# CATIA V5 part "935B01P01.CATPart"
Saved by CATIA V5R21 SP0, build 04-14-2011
Part number: 935B01P01
Bounding box of the stored display mesh (mm): x -17.1 to 17.1, y -76.2 to 76.2, z -4.4 to 4.4
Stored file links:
  C:\Users\ALI OZGUN\Desktop\alhan\935B01P01.CATPart
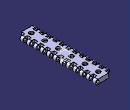
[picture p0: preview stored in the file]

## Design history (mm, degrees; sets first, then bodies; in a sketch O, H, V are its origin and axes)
Body1 (main body)
  Sketch1 on zx-plane, origin (0, 0, 0), H (-1, 0, 0), V (0, 0, 1)
    construction line L1 (-12.7, 0) -> (12.7, 0)
    point P1 (-12.7, 0)
    line L2 (-12.7, 4.4) -> (12.7, 4.4)
    line L3 (12.7, -4.4) -> (-12.7, -4.4)
    arc A1 centre (12.7, 0) radius 4.4 from (12.7, 4.4) to (12.7, -4.4) cw
    arc A2 centre (-12.7, 0) radius 4.4 from (-12.7, -4.4) to (-12.7, 4.4) cw
    distance L1 L2 = 4.4
    length L1 = 25.4
    distance P1 V = 12.7
    coincidence: P1 H
    horizontal: L1 H
    tangency: A1 L2, A2 L2, A1 L3, A2 L3
  Pad1: profile Sketch1, direction (0, 1, 0), length 76.2, mirrored extent
  Sketch2 on face of Pad1 from Sketch1.L2, origin (0, 0, 4.4), H (1, 0, 0), V (0, 1, 0)
    line L1 (-22.3127, -63.5) -> (-9.75, -63.5)
    line L2 (-9.75, -63.5) -> (-9.75, -70.6)
    line L3 (-9.75, -70.6) -> (-22.3127, -70.6)
    line L4 (-22.3127, -70.6) -> (-22.3127, -63.5)
    line L5 (24.6678, -76.95) -> (9.75, -76.95)
    line L6 (9.75, -76.95) -> (9.75, -69.85)
    line L7 (9.75, -69.85) -> (24.6678, -69.85)
    line L8 (24.6678, -69.85) -> (24.6678, -76.95)
    reference projected line E1 (-12.7, -76.2) -> (12.7, -76.2) from edge [start face of Pad1 | face of Pad1 from Sketch1.L2]
    reference projected line E2 (-12.7, -76.2) -> (12.7, -76.2) from edge [start face of Pad1 | face of Pad1 from Sketch1.L2]
    distance L3 E1 = 5.6
    length L4 = 7.1
    distance L7 L5 = 7.1
    distance L5 E2 = 0.75
    distance L2 L6 = 19.5
    distance L2 V = 9.75
    horizontal: L1 H, L3 H, L5 H, L7 H
    vertical: L2 V, L4 V, L6 V, L8 V
  Pocket1: profile Sketch2, direction (0, 0, -1), length 76.2
  RectPattern1: of Pocket1, direction 1 instances 12, spacing 12.7, along axis of face of Pad1 from Sketch1.A2
  Sketch3 on face of Pad1 from Sketch1.L3, origin (0, 0, -4.4), H (1, 0, 0), V (0, -1, 0)
    line L1 (-6.5, -54.6) -> (6.5, -54.6)
    line L2 (6.5, -54.6) -> (6.5, -73.7)
    line L3 (6.5, -73.7) -> (-6.5, -73.7)
    line L4 (-6.5, -73.7) -> (-6.5, -54.6)
    construction line L5 (-4.5, -51.1) -> (4.5, -51.1)
    point P5 (-4.5, -51.1)
    line L6 (-4.5, -49.6) -> (4.5, -49.6)
    line L7 (4.5, -52.6) -> (-4.5, -52.6)
    arc A1 centre (4.5, -51.1) radius 1.5 from (4.5, -49.6) to (4.5, -52.6) cw
    arc A2 centre (-4.5, -51.1) radius 1.5 from (-4.5, -52.6) to (-4.5, -49.6) cw
    reference projected line E1 (12.7, -76.2) -> (-12.7, -76.2) from edge [face of Pad1 from Sketch1.L3 | end face of Pad1]
    distance L5 L6 = 1.5
    distance L1 L3 = 19.1
    distance L4 L2 = 13
    distance L4 V = 6.5
    distance E1 L3 = 2.5
    distance P5 V = 4.5
    length L5 = 9
    distance L7 L1 = 2
    horizontal: L1 H, L3 H, L5 H
    vertical: L2 V, L4 V
    tangency: A1 L6, A2 L6, A1 L7, A2 L7
  Pocket2: profile Sketch3, direction (0, 0, 1), length 6
  RectPattern2: of Pocket2, direction 1 instances 6, spacing 25.8, along axis of face of Pad1 from Sketch1.A2 reversed
  Sketch4 on zx-plane, origin (0, 0, 0), H (-1, 0, 0), V (0, 0, 1)
    circle A1 centre (12.7, 0) radius 2.3
    point P1 (12.7, 0)
    circle A2 centre (-12.7, 0) radius 2.3
    point P2 (-12.7, 0)
    reference projected arc E1 centre (12.7, 0) radius 4.4 from (12.7, -4.4) to (12.7, 4.4) ccw from edge [face of RectPattern1 | face of Pad1 from Sketch1.A1]
    reference projected arc E2 centre (-12.7, 0) radius 4.4 from (-12.7, 4.4) to (-12.7, -4.4) ccw from edge [face of Pad1 from Sketch1.A2 | end face of Pad1]
    radius A1 = 2.3
    radius A2 = 2.3
    coincidence: P1 H, P2 H
    concentricity: P1 E1, A2 E2
  Pocket3: profile Sketch4, direction (0, -1, 0), length 97.8, mirrored extent
  Body2
    Solid1: linked copy from another document
    Symmetry1: Reference yz-plane, ToTransfor Solid1
    Translate1: Direction edge [face of Pocket1 from Sketch2.L2 | face of Pad1 from Sketch1.L3], Length 6.35, ToTransfor Symmetry1
    Body3
      Sketch5 on face of RectPattern1, origin (9.75, 0, 0), H (0, 1, 0), V (0, 0, 1)
      Pad2: profile Sketch5, direction (1, 0, 0), length 12
      Sketch6 on face of Pad2, origin (0, 69.85, 0), H (-1, 0, 0), V (0, 0, 1)
        point P2 (-21.75, 4.4)
        arc A1 centre (-16.4898, 1.5645) radius 9 from (-9.75, -4.4) to (-7.9481, 4.4) ccw
        point P8 (-21.75, 4.4)
        construction line L1 (-9.75, 4.4) -> (-21.75, 4.4)
        line L2 (-7.9481, 4.4) -> (-21.75, 4.4)
        line L3 (-9.75, -4.4) -> (-21.75, -4.4)
        line L4 (-21.75, -4.4) -> (-21.75, 4.4)
        radius A1 = 9
        coincidence: P2 P8
      Pad3: profile Sketch6, direction (0, 1, 0), up to face of Pad2
      RectPattern3: of the body so far, direction 1 instances 12, spacing 12.7, along edge [face of Pad3 | face of Pad3] reversed
    Add1: tool Body3
  Remove1: tool Body2
  Sketch7 on face of Pad1 from Sketch1.L2, origin (0, 0, 4.4), H (1, 0, 0), V (0, 1, 0)
    circle A1 centre (0, -64.85) radius 4
    point P1 (0, -64.85)
    reference projected line E1 (-6.5, -55.3) -> (6.5, -55.3) from edge [face of RectPattern2 | face of RectPattern2]
    reference projected line E2 (6.5, -74.4) -> (-6.5, -74.4) from edge [face of Pad1 from Sketch1.L3 | face of RectPattern2]
    reference projected line E3 (-6.5, -55.3) -> (6.5, -55.3) from edge [face of RectPattern2 | face of RectPattern2]
    circle A2 centre (0, -39.05) radius 4
    circle A3 centre (0, -13.25) radius 4
    circle A4 centre (0, 12.55) radius 4
    circle A5 centre (0, 38.35) radius 4
    circle A6 centre (0, 64.15) radius 4
    radius A1 = 4
    distance P1 E1 = 9.55
    distance E2 E3 = 19.1 (reference)
    coincidence: P1 V
  Pocket4: profile Sketch7, direction (0, 0, -1), length 6
Body4
  Solid2: linked copy from another document
  Translate2: Direction yz-plane, Length 25.4, ToTransfor Solid2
